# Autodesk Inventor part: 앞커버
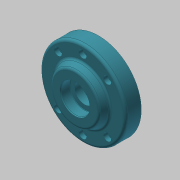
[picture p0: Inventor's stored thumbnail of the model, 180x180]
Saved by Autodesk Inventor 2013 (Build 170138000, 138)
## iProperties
Company: 한국ATC센터
Created: 2015-12
Part Number: 앞커버
Document SubType Name: Modeling
Designer: 앞커버
Density: 2.71 g/cm^3
Mass: 114.339 g
Surface Area: 117.889 cm^2
Volume: 42.1916 cm^3
Material: 알루미늄 6061
Author: mdu
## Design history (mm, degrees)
sketch "스케치1"
  geometry: L1 (-11.5, 0)-(11.5, 0); L2 (11.5, 0)-(11.5, 22.5); L3 (11.5, 22.5)-(6.5, 22.5); L4 (6.5, 22.5)-(6.5, 32.5); L5 (6.5, 32.5)-(-5.5, 32.5); L6 (-5.5, 32.5)-(-5.5, 21); L7 (-5.5, 21)-(-11.5, 18.202); L8 (-11.5, 18.202)-(-11.5, 0); 2 further points
  constraints: 16 end point, 3 parallel, 3 perpendicular, 1 coincident, 1 horizontal, 1 midpoint
  dimensions: "d0" = 23 distance of L1.start L1.end; "d1" = 65 diameter of L5 L1; "d2" = 45 diameter of L3 L1; "d3" = 42 diameter of L6.end L1; "d4" = 115 deg angle of L7 L6; "d5" = 12 distance of L4.end L5.end; "d6" = 5 distance of L2.end L3.end
revolve "회전1" sketch "스케치1" stored, may be unused: angle "d7" = 90 deg
sketch "스케치2"
  geometry: L1 (0, 0)-(32.5, 0); L2 (0, 0)-(0, 26.5); 1 further point
  constraints: 4 end point, 1 horizontal, 1 horizontal alignment, 1 other
  dimensions: "d8" = 90 deg angle of L1 L2; "d9" = 26.5 distance of L1.start L2.end
hole "구멍1" sketch "스케치2" at (0, 26.5) diameter "d10" = 3.4; stored, may be unused: countersink angle "d14" = 90 deg, drill point angle "d16" = 118 deg; dims "d11" = 6, "d12" = 6, "d13" = 3.3, "d15" = 8
fillet "모깎기1" dims "d20" = 2
hole "구멍2" diameter "d23" = 15; stored, may be unused: countersink angle "d27" = 90 deg, drill point angle "d29" = 118 deg; dims "d21" = 10, "d22" = 10, "d24" = 6, "d25" = 32, "d26" = 10, "d28" = 8
hole "구멍3" diameter "d32" = 22; stored, may be unused: countersink angle "d36" = 90 deg, drill point angle "d38" = 0 deg; dims "d33" = 6, "d34" = 32, "d35" = 10, "d37" = 7.3, "d46" = 10, "d47" = 10
chamfer "모따기1" distance "d39" = 1; stored, may be unused: second distance "d40" = 2, angle "d41" = 45 deg
chamfer "모따기2" distance "d43" = 0.7; stored, may be unused: second distance "d44" = 2, angle "d45" = 30 deg
fillet "모깎기2" dims "d42" = 0.3
node "솔리드1"
pattern_circular "원형 패턴1" dims angle "d18" = 360 deg
